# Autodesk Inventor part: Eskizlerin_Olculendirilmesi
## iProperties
Company: Autodesk, Inc.
Shininess: 64.0
Length Units: 11269
Angle Units: 11279
Time Units: 11290
Mass Units: 11283
Length Display Precision: 3
Angle Display Precision: 2
Compacted: True
Part Number: Eskizlerin_Olculendirilmesi
Document SubType Name: Modeling
Created: 2003-11
Catalog Web Link: www.autodesk.com
Designer: Administrator
Manufacturer: Standard
Standards Organization: Custom
Density: 1 g/cm^3
Density: 0.0
Volumn: 0.0
Area: 0.0
PropertySet Name: Model Information
Control State: 0
Master: False
Checked Out: False
Author: Administrator
